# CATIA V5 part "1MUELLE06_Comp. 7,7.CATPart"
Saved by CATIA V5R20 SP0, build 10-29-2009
Part number: 1MUELLE06_Comp. 7,7
Revision: ANY
Definition: UNKNOWN
Nomenclature: 1MUELLE06_Comp. 7,7
Source: Unknown
Bounding box of the stored display mesh (mm): x -4.9 to 4.9, y -4.9 to 4.9, z -0.55 to 8.249
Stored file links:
  C:\Users\Utente\Desktop\IO LAVORO\3D X SITO CF\CUMSA\3D files AE\AE 062430\1MUELLE06_Comp. 7,7.CATPart
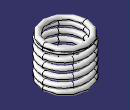
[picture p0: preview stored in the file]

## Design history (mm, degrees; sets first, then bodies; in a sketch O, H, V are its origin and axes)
Set1 "FacciaKO#NONE#13269"
  DatumSurface1 "Sup13269_1"
  Circle1 "Crv13269_1": stored without definition
Set2 "FacciaKO#NONE#23906"
  DatumSurface2 "Sup23906_1"
  Circle2 "Crv23906_1": stored without definition
Set3 "FacciaKO#NONE#10532"
  DatumSurface3 "Sup10532_1"
  Circle3 "Crv10532_1": stored without definition
Body1 "Cortar-Extruir3" (main body)
  Solid1: solid without history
